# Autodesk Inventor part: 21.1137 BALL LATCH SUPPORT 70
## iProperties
Created: 2007-03
Part Number: 21.1137 BALL LATCH SUPPORT 70
Document SubType Name: Modeling
Designer: Andy Moles
Material: Aluminum-6061
Mass: 50.0451 g
Surface Area: 97.4227 cm^2
Volume: 18.4668 cm^3
Density: 2.71 g/cm^3
Author: Andy Moles
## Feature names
1. Extrusion1
2. Extrusion2
3. Extrusion3
